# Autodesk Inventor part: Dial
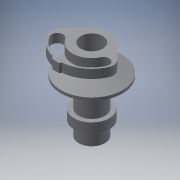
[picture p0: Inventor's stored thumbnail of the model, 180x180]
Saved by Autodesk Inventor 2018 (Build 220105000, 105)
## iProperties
Shininess: 64.0
Length Units: 11272
Angle Units: 11279
Time Units: 11290
Mass Units: 11286
Length Display Precision: 3
Angle Display Precision: 2
Compacted: True
Created: 2001-11
Part Number: Dial
Document SubType Name: Modeling
Designer: Autodesk, Inc.
Mass: 1.0296 g
Surface Area: 19.0281 cm^2
Volume: 1.0296 cm^3
Density: 1 g/cm^3
Material: Generic
Appearance: Grey (Light)
Density: 0.0
Volumn: 0.0
Area: 0.0
PropertySet Name: Model Information
Control State: 0
Master: False
Checked Out: False
Author: Autodesk, Inc.
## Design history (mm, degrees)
sketch "Sketch1"
  geometry: L1 (120.263, 98.09)-(121.533, 98.09); L2 (121.533, 100.63)-(121.533, 98.09); L3 (121.533, 100.63)-(125.343, 100.63); L4 (125.343, 101.458)-(125.343, 100.63); L5 (119.755, 103.715)-(125.343, 101.458); L6 (119.755, 106.472)-(119.755, 103.715); L7 (119.755, 106.472)-(125.851, 106.472); L8 (125.851, 106.472)-(125.851, 109.012); L9 (116.453, 109.012)-(125.851, 109.012); L10 (116.453, 109.012)-(116.453, 86.66); L11 (116.453, 86.66)-(117.215, 86.66); L12 (117.215, 86.66)-(117.215, 85.644); L13 (117.215, 85.644)-(120.263, 85.644); L14 (120.263, 89.708)-(120.263, 85.644); L15 (120.263, 89.708)-(121.533, 89.708); L16 (121.533, 92.502)-(121.533, 89.708); L17 (120.263, 92.502)-(121.533, 92.502); L18 (120.263, 98.09)-(120.263, 92.502); L19 (116.453, 109.012)-(116.453, 86.66)
  constraints: 38 end point, 9 vertical, 8 horizontal, 2 collinear, 1 other
  dimensions: "d1" = 9.398 distance of L9.start L8.end; "d3" = 22.352 distance of L9.start L10.end; "d5" = 2.54 distance of L7.end L8.end; "d11" = 10.922 vertical distance of L9.start L1.end; "d13" = 8.382 vertical distance of L9.start L3.end; "d15" = 16.51 vertical distance of L16.start L8.end; "d17" = 19.304 vertical distance of L14.start L8.end; "d19" = 1.016 distance of L11.end L12.end; "d23" = 8.89 horizontal distance of L10.end L3.end; "d25" = 0.762 distance of L10.end L11.end; "d27" = 3.048 distance of L12.end L13.end; "d51" = 6.604 diameter of L6 L10
revolve "RevolutionFull1" sketch "Sketch1" stored, may be unused: angle "d28" = 360 deg
sketch "Sketch2"
  geometry: C1 r 3.302 at (0, 0) reference; A1 r 5.588 centre (0, 0) between (-4.761, -2.925) and (5.042, -2.408); A2 r 1.651 centre (6.532, -3.12) between (7.607, -1.867) and (5.042, -2.408); A3 r 1.651 centre (6.532, -3.12) between (8.022, -3.832) and (7.607, -1.867); A4 r 8.89 centre (0, 0) between (-7.575, -4.654) and (8.022, -3.832); A5 r 1.651 centre (-6.168, -3.79) between (-7.335, -2.622) and (-7.575, -4.654); A6 r 1.651 centre (-6.168, -3.79) between (-4.761, -2.925) and (-7.335, -2.622)
  constraints: 12 point on circle, 6 centre point, 5 tangent, 4 concentric
  dimensions: "d34" = 12.7 horizontal distance of A6.centre A3.centre; "d36" = 5.588 radius of A1; "d38" = 8.89 radius of A4
extrude "ExtrusionToFace1" cut sketch "Sketch2" stored distance "d39" = 3.302; taper "d40" = 0 deg
sketch "Sketch3"
  geometry: L1 (25.051, 17.256)-(-16.734, 17.256); L2 (25.051, -5.225)-(25.051, 17.256); L3 (25.051, -5.225)-(10.165, -5.225); L4 (3.682, 3.682)-(9.59, -2.226); L5 (-3.682, 3.682)-(-9.632, -2.268); L6 (-16.734, -6.364)-(-10.09, -5.233); L7 (-16.734, 17.256)-(-16.734, -6.364); C1 r 9.398 at (0, 0) reference; A1 r 2.721 centre (7.666, -4.15) between (10.165, -5.225) and (9.59, -2.226); A2 r 5.207 centre (0, 0) between (3.682, 3.682) and (-3.682, 3.682); A3 r 2.54 centre (-7.836, -4.064) between (-9.632, -2.268) and (-10.09, -5.233)
  constraints: 14 end point, 6 point on circle, 4 tangent, 3 centre point, 2 horizontal, 2 vertical, 1 concentric
extrude "ExtrusionBlind1" cut sketch "Sketch3" distance "d41" = 2.54; taper "d42" = 0 deg
sketch "Sketch4"
  geometry: L1 (-1.536, -9.906)-(0.457, -9.906); L2 (0.457, -9.906)-(0.734, -9.369); L3 (-1.536, -9.906)-(-2.352, -9.099); A1 r 9.398 centre (0, 0) between (-9.214, -1.85) and (9.214, -1.85) reference
  constraints: 6 end point, 2 point on circle, 1 horizontal, 1 other
  dimensions: "d44" = 9.906 dimension on L1.start
extrude "ExtrusionToPlane1" join sketch "Sketch4" stored distance "d45" = 3.302; taper "d46" = 0 deg
extrude "ExtrusionThru1" cut extent not by distance; stored distance "d49" = 3.302; taper "d50" = 0 deg
  node "Sketch5" dims "d48" = 6.35
fillet "Fillet1" dims "d52" = 2.54
body "Solid1"
other parameters: "d0" = 9.398 (derived), "d2" = 22.352 (derived), "d4" = 2.54 (derived), "d6" = 5.08 (derived), "d8" = 6.604 (derived), "d10" = 10.922 (derived), "d12" = 8.382 (derived), "d14" = 16.51 (derived), "d16" = 19.304 (derived), "d18" = 1.016 (derived), "d20" = 158 deg (derived), "d22" = 8.89 (derived), "d24" = 0.762 (derived), "d26" = 3.048 (derived), "d29" = 0, "d30" = 0, "d31" = 0, "d32" = 0, "d33" = 12.7 (derived), "d35" = 5.588 (derived), "d37" = 8.89 (derived), "d43" = 9.906 (derived), "d47" = 6.35 (derived)
